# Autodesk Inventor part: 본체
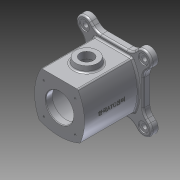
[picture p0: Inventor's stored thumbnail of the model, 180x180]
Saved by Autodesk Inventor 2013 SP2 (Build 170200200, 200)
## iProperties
Created: 2022-01
Part Number: 본체
Material: 알루미늄 6061
Document SubType Name: Modeling
Designer: aa
Density: 2.71 g/cm^3
Mass: 1230.9 g
Surface Area: 908.329 cm^2
Volume: 454.205 cm^3
Author: aa
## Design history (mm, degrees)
sketch "스케치1"
  geometry: L1 (32.942, 45)-(-32.942, 45); L2 (-45, -45)-(45, 45); L3 (45, -45)-(-45, 45); A1 r 90 centre (-45, 0) between (37.029, -37.029) and (32.942, 45); A2 r 90 centre (0, 45) between (-37.029, -37.029) and (37.029, -37.029); A3 r 90 centre (45, 0) between (-32.942, 45) and (-37.029, -37.029); 6 further points
  constraints: 7 point on circle, 6 end point, 5 midpoint, 3 centre point, 3 horizontal alignment, 3 vertical alignment, 1 coincident
  dimensions: "d4" = 90 distance of L3.end L2.end; "d5" = 90 distance of L2.end L3.start; "d49" = 90 radius of A1; "d50" = 90 radius of A2; "d51" = 90 radius of A3; "d52" = 65.88457 distance of L1.start L1.end; "d53" = 74.05881 distance of A1.start A2.start; "d54" = 90 distance of A3.centre A1.centre; "d55" = 90 horizontal distance of L2.start L2.end; "d56" = 90 horizontal distance of L3.start L3.end; "d57" = 45 distance of A2.centre L2.end
extrude "돌출1" new body sketch "스케치1" stored distance "d7" = 110; taper "d8" = 0 deg
sketch "스케치2"
  geometry: L1 (0, 55)-(0, -55); L2 (25, 43)-(37, 43); L3 (37, 43)-(37, -43); L4 (37, -43)-(25, -43); L5 (45, 55)-(-37.029, 55) reference; L6 (-37.029, -55)-(45, -55) reference; L7 (45, -55)-(45, 55) reference; L8 (25, 43)-(25, 55); L9 (25, -43)-(25, -55); L10 (25, 55)-(0, 55); L11 (25, -55)-(0, -55); 3 further points
  constraints: 16 end point, 3 perpendicular, 2 coincident, 2 point on line, 1 midpoint
  dimensions: "d10" = 110 distance of L1.start L1.end; "d12" = 86 distance of L2.end L3.end; "d13" = 74 diameter of L3 L1; "d58" = 12 distance of L2.start L8.end; "d59" = 12 distance of L4.end L9.end; "d60" = 50 diameter of L8 L1; "d61" = 50 diameter of L9 L1
revolve "회전1" sketch "스케치2" stored, may be unused: angle "d16" = 90 deg
node "작업 평면1"
sketch "스케치3"
  geometry: L1 (32.942, -55)-(-32.942, -55) reference; C1 r 20 at (0, 6); 3 further points
  constraints: 1 centre point, 1 vertical alignment
  dimensions: "d18" = 40 diameter of C1; "d19" = 61 distance from line of C1.centre L1
extrude "돌출2" join sketch "스케치3" stored distance "d20" = 110; taper "d21" = 10 deg
sketch "스케치4"
  geometry: C1 r 20 at (0, 0) reference; C2 r 12 at (0, 0); 1 further point
  constraints: 1 centre point, 1 coincident
  dimensions: "d22" = 24 diameter of C2
extrude "돌출3" cut sketch "스케치4" distance "d23" = 13; taper "d24" = 0 deg
sketch "스케치6"
  geometry: L1 (32.942, 45)-(-32.942, 45) reference; L2 (-53, -53)-(53, -53); L3 (53, -53)-(53, 53); L4 (53, 53)-(-53, 53); L5 (-53, 53)-(-53, -53); L6 (-53, -53)-(53, 53); L7 (53, -53)-(-53, 53); L8 (-63.607, 42.393)-(-53, 31.787); L9 (-42.393, 63.607)-(-31.787, 53); L10 (42.393, 63.607)-(31.787, 53); L11 (63.607, 42.393)-(53, 31.787); L12 (-63.607, -42.393)-(-53, -31.787); L13 (-42.393, -63.607)-(-31.787, -53); L14 (63.607, -42.393)-(53, -31.787); L15 (42.393, -63.607)-(31.787, -53); L16 (-45, -45)-(45, 45); L17 (45, -45)-(-45, 45); C1 r 25 at (0, 0) reference; C2 r 25 at (0, 0); A1 r 15 centre (-53, 53) between (-42.393, 63.607) and (-63.607, 42.393); A2 r 15 centre (-53, -53) between (-63.607, -42.393) and (-42.393, -63.607); A3 r 15 centre (53, -53) between (42.393, -63.607) and (63.607, -42.393); A4 r 15 centre (53, 53) between (63.607, 42.393) and (42.393, 63.607); A5 r 90 centre (0, 45) between (-37.029, -37.029) and (37.029, -37.029) reference; A6 r 90 centre (-45, 0) between (37.029, -37.029) and (32.942, 45) reference; 8 further points
  constraints: 32 end point, 10 midpoint, 8 parallel, 8 point on circle, 8 point on line, 8 tangent, 5 centre point, 5 coincident, 3 perpendicular, 2 horizontal alignment, 2 vertical alignment, 1 concentric, 1 horizontal
  dimensions: "d28" = 106 distance of L4.end L3.end; "d29" = 106 distance of L3.end L2.end; "d36" = 30 distance between parallel lines of L9 L8; "d39" = 30 diameter of A3; "d40" = 30 distance between parallel lines of L11 L10; "d41" = 30 distance between parallel lines of L13 L12; "d62" = 90 distance of L17.end L16.end; "d63" = 90 distance of L16.end L17.start; "d64" = 90 horizontal distance of L17.start L17.end; "d65" = 90 horizontal distance of L16.start L16.end; "d66" = 98 distance from line of L2 A5.centre; "d67" = 98 distance from line of L3 A6.centre
extrude "돌출5" join sketch "스케치6" distance "d34" = 12; taper "d35" = 0 deg
sketch "스케치8"
  geometry: L1 (0, 0)-(28.284, 28.284); L2 (0, 0)-(40, 0); C1 r 25 at (0, 0) reference; 1 further point
  constraints: 4 end point, 1 coincident, 1 equal length, 1 horizontal
  dimensions: "d69" = 40 distance of L1.start L1.end; "d70" = 45 deg angle of L2 L1
hole "구멍2" sketch "스케치8" at (28.284, 28.284) diameter "d71" = 3.242; stored, may be unused: countersink angle "d75" = 90 deg, drill point angle "d77" = 118 deg; dims "d72" = 9, "d73" = 4, "d74" = 2, "d76" = 11
fillet "모깎기1" dims "d81" = 20
fillet "모깎기2" dims "d82" = 3
fillet "모깎기3" dims "d83" = 3
chamfer "모따기1" distance "d84" = 1; stored, may be unused: second distance "d85" = 2, angle "d86" = 45 deg
node "작업 평면2"
sketch "스케치9"
  geometry: L1 (43.448, 55)-(-35.954, 55) reference; L2 (23.503, -55)-(-23.503, -55) reference; L3 (55, 26)-(55, -14) reference; 2 further points
  constraints: 1 other
  dimensions: "d89" = 61 distance from line of L2 point (0, 6); "d90" = 55 distance from line of point (0, 6) L3
feature "엠보싱1" sketch "스케치9" dims "d5" = 90, "d91" = 0.5, "d92" = 0
sketch "스케치10"
  geometry: A1 r 12 centre (-53, 53) between (-44.515, 61.485) and (-61.485, 44.515) reference; A2 r 12 centre (-53, -53) between (-61.485, -44.515) and (-44.515, -61.485) reference; A3 r 12 centre (53, -53) between (44.515, -61.485) and (61.485, -44.515) reference; A4 r 12 centre (53, 53) between (61.485, 44.515) and (44.515, 61.485) reference; 5 further points
  constraints: 4 coincident
hole "구멍3" sketch "스케치10" at (-53, 53), (-53, -53), (53, -53), (53, 53) diameter "d93" = 9; stored, may be unused: countersink angle "d97" = 90 deg, drill point angle "d99" = 118 deg; dims "d94" = 9, "d95" = 18, "d96" = 2, "d98" = 11
node "작업 평면3"
sketch "스케치11"
  geometry: C1 r 15 at (0, 0); 1 further point
  constraints: 1 centre point
  dimensions: "d101" = 30 diameter of C1
extrude "돌출6" cut sketch "스케치11" stored distance "d102" = 10; taper "d103" = 0 deg
chamfer "모따기2" distance "d104" = 1; stored, may be unused: second distance "d105" = 2, angle "d106" = 45 deg
fillet "모깎기4" dims "d107" = 3
node "솔리드1"
pattern_circular "원형 패턴1" dims angle "d79" = 360 deg
mirror "대칭1"
other parameters: "d17" = 55, "d100" = -13
